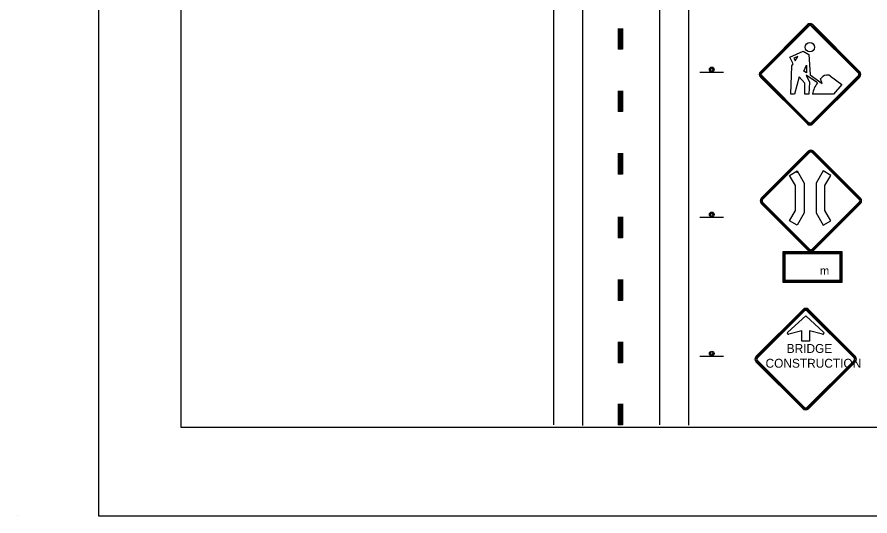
# Model space of a CAD drawing. Extents: x 1062 to 1288, y 239 to 518.
# Drawn here: x 1061.7 to 1165.3, y 238.9 to 299.6 of the extents above; entities that cross this region are included whole.
import ezdxf

# ---------------------------------------------------------------- set-up
doc = ezdxf.new("R2010")
doc.units = 0
for name, color, linetype in [('Level 10', 7, 'Continuous'), ('Level 17', 7, 'Continuous'), ('Level 44', 7, 'Continuous'), ('Level 60', 7, 'Continuous')]:
    doc.layers.add(name, color=color, linetype=linetype)

# ---------------------------------------------------------------- blocks, each defined once
blk = doc.blocks.new('WDA024')
at = {"layer": 'Level 17'}
for p, q in [((50.34, 50.34), (2.69, 2.69)), ((51.05, 49.64), (3.39, 1.98)), ((51.76, 48.94), (4.1, 1.27)), ((101.97, 1.27), (54.3, 48.94)), ((102.67, 1.98), (55.01, 49.64)), ((103.38, 2.69), (55.72, 50.34)), ((40.54, 24.59), (32.82, 20.13)), ((32.82, 20.13), (38.86, 9.73)), ((47.74, 12.11), (40.54, 24.59)), ((59.76, 12.11), (66.96, 24.59)), ((66.96, 24.59), (74.62, 20.13)), ((74.62, 20.13), (68.64, 9.73)), ((38.86, 9.73), (38.86, -15.46)), ((47.74, -17.84), (47.74, 12.11)), ((59.76, -17.84), (59.76, 12.11)), ((68.64, 9.73), (68.64, -15.46)), ((0, 0), (0, 0)), ((2.69, -2.69), (50.34, -50.35)), ((3.39, -1.98), (51.05, -49.64)), ((4.1, -1.27), (51.76, -48.93)), ((54.3, -48.93), (101.97, -1.27)), ((55.01, -49.64), (102.67, -1.98)), ((55.72, -50.35), (103.38, -2.69)), ((38.86, -15.46), (32.82, -25.86)), ((68.64, -15.46), (74.62, -25.86)), ((32.82, -25.86), (40.54, -30.27)), ((40.54, -30.27), (47.74, -17.84)), ((66.96, -30.27), (59.76, -17.84)), ((74.62, -25.86), (66.96, -30.27)), ((66.96, -30.27), (67.36, -28.58))]:
    blk.add_line(p, q, dxfattribs=at)
for centre, radius, start, end in [((53.03, 47.66), 3.8, 45, 135), ((53.03, 47.66), 2.8, 45, 135), ((53.03, 47.66), 1.8, 45, 135), ((5.37, 0), 3.8, 135, 225), ((5.37, 0), 2.8, 135, 225), ((5.37, 0), 1.8, 135, 225), ((100.69, 0), 1.8, 315, 45), ((100.69, 0), 2.8, 315, 45), ((100.69, 0), 3.8, 315, 45), ((53.03, -47.66), 3.8, 225, 315), ((53.03, -47.66), 2.8, 225, 315), ((53.03, -47.66), 1.8, 225, 315)]:
    blk.add_arc(centre, radius, start, end, dxfattribs=at)
blk = doc.blocks.new('WDB04T')
at = {"layer": 'Level 17'}
for points in [[(60.004, 0.004), (0.004, 0.004), (0.004, -30.671), (60.004, -30.671)], [(59.004, -0.996), (1.004, -0.996), (1.004, -29.671), (59.004, -29.671)], [(58.004, -1.996), (2.004, -1.996), (2.004, -28.671), (58.004, -28.671)]]:
    blk.add_lwpolyline(points, close=True, dxfattribs=at)
blk.add_text('m', height=8.373, dxfattribs=at).set_placement((37.562, -23.321))

msp = doc.modelspace()

# ---------------------------------------------------------------- linework, layer by layer
at = {"layer": 'Level 10'}
for p, q in [((1143.33, 249.99), (1143.33, 410.9)), ((1126.93, 250.01), (1126.93, 401.62)), ((1139.81, 250.01), (1139.81, 380.51)), ((1130.44, 249.95), (1130.44, 373.79))]:
    msp.add_line(p, q, dxfattribs=at)
at = {"layer": 'Level 17'}
for p, q in [((1157.75, 298.68), (1152.03, 292.96)), ((1164.11, 292.96), (1158.39, 298.68)), ((1157.83, 298.59), (1152.11, 292.88)), ((1157.92, 298.51), (1152.2, 292.79)), ((1163.94, 292.79), (1158.22, 298.51)), ((1164.03, 292.88), (1158.31, 298.59)), ((1151.71, 292.64), (1151.71, 292.64)), ((1152.11, 292.4), (1157.83, 286.68)), ((1152.2, 292.48), (1157.92, 286.76)), ((1158.22, 286.76), (1163.94, 292.48)), ((1158.31, 286.68), (1164.03, 292.4)), ((1160.56, 292.41), (1161.93, 291.41)), ((1160.56, 292.41), (1161.93, 291.41)), ((1152.03, 292.31), (1157.75, 286.6)), ((1158.39, 286.6), (1164.11, 292.31)), ((1159.32, 292.09), (1159.62, 292.36)), ((1159.32, 292.09), (1159.62, 292.36)), ((1151.49, 258.32), (1157.21, 264.04)), ((1151.58, 258.24), (1157.3, 263.96)), ((1151.66, 258.15), (1157.38, 263.87)), ((1157.69, 263.87), (1163.41, 258.15)), ((1157.77, 263.96), (1163.49, 258.24)), ((1157.86, 264.04), (1163.58, 258.32)), ((1155.47, 261.04), (1155.47, 261.04)), ((1155.47, 261.04), (1155.47, 261.04)), ((1155.47, 261.04), (1155.47, 261.04)), ((1151.17, 258), (1151.17, 258)), ((1157.21, 251.96), (1151.49, 257.68)), ((1157.3, 252.04), (1151.58, 257.76)), ((1157.38, 252.13), (1151.66, 257.85)), ((1163.41, 257.85), (1157.69, 252.13)), ((1163.49, 257.76), (1157.77, 252.04)), ((1163.58, 257.68), (1157.86, 251.96))]:
    msp.add_line(p, q, dxfattribs=at)
for points in [[(1158.96, 291.59), (1157.58, 292.54), (1157.98, 291.7), (1157.93, 290.24), (1157.45, 290.24), (1157.42, 291.56), (1156.75, 292.33), (1156.17, 290.24), (1155.75, 290.24), (1155.87, 293.69), (1156.03, 293.93), (1155.6, 294.74), (1157.22, 295.46), (1157.91, 295.06), (1158.07, 292.59), (1159.55, 291.52), (1159.32, 292.09)], [(1161.93, 291.41), (1160.92, 290.24), (1158.35, 290.24)], [(1155.35, 261.27), (1157.54, 263.26), (1159.72, 261.27)], [(1155.35, 261.27), (1157.54, 263.26), (1159.72, 261.27)], [(1155.35, 261.27), (1157.54, 263.26), (1159.72, 261.27)], [(1159.59, 261.04), (1157.99, 261.45), (1157.99, 260.2), (1157.08, 260.2), (1157.08, 261.45), (1155.47, 261.04)], [(1159.59, 261.04), (1157.99, 261.45), (1157.99, 260.2), (1157.08, 260.2), (1157.08, 261.45), (1155.47, 261.04)], [(1159.59, 261.04), (1157.99, 261.45), (1157.99, 260.2), (1157.08, 260.2), (1157.08, 261.45), (1155.47, 261.04)]]:
    msp.add_lwpolyline(points, dxfattribs=at)
for points in [[(1156.08, 294.59), (1156.25, 294.29), (1156.57, 294.79)], [(1157.32, 293.04), (1157.62, 293.75), (1157.65, 292.84)]]:
    msp.add_lwpolyline(points, close=True, dxfattribs=at)
msp.add_circle((1158.05, 295.93), 0.569, dxfattribs=at)
for centre, radius, start, end in [((1158.07, 298.36), 0.456, 45, 135), ((1158.07, 298.36), 0.336, 45, 135), ((1158.07, 298.36), 0.216, 45, 135), ((1152.35, 292.64), 0.456, 135, 225), ((1152.35, 292.64), 0.336, 135, 225), ((1152.35, 292.64), 0.216, 135, 225), ((1160.12, 291.8), 0.749, 53.9362, 131.97), ((1160.12, 291.8), 0.749, 53.9362, 131.97), ((1163.79, 292.64), 0.216, 315, 45), ((1163.79, 292.64), 0.336, 315, 45), ((1163.79, 292.64), 0.456, 315, 45), ((1161.82, 289.48), 3.55, 143.5617, 167.6366), ((1158.07, 286.92), 0.456, 225, 315), ((1158.07, 286.92), 0.336, 225, 315), ((1158.07, 286.92), 0.216, 225, 315), ((1157.54, 263.72), 0.456, 45, 135), ((1157.54, 263.72), 0.336, 45, 135), ((1157.54, 263.72), 0.216, 45, 135), ((1155.44, 261.17), 0.137, 132.3048, 284.4075), ((1155.44, 261.17), 0.137, 132.3048, 284.4075), ((1155.44, 261.17), 0.137, 132.3048, 284.4075), ((1159.63, 261.17), 0.137, 255.5925, 47.6952), ((1159.63, 261.17), 0.137, 255.5925, 47.6952), ((1159.63, 261.17), 0.137, 255.5925, 47.6952), ((1151.82, 258), 0.456, 135, 225), ((1151.82, 258), 0.336, 135, 225), ((1163.25, 258), 0.336, 315, 45), ((1163.25, 258), 0.456, 315, 45), ((1151.82, 258), 0.216, 135, 225), ((1163.25, 258), 0.216, 315, 45), ((1157.54, 252.28), 0.456, 225, 315), ((1157.54, 252.28), 0.336, 225, 315), ((1157.54, 252.28), 0.216, 225, 315)]:
    msp.add_arc(centre, radius, start, end, dxfattribs=at)
at = {"layer": 'Level 44'}
for p, q in [((1135.25, 295.7), (1134.73, 295.7)), ((1144.66, 292.92), (1147.56, 292.92)), ((1135.25, 288.1), (1134.73, 288.1)), ((1135.25, 280.5), (1134.73, 280.5)), ((1144.66, 275.27), (1147.56, 275.27)), ((1135.25, 272.75), (1134.73, 272.75)), ((1135.25, 265.15), (1134.73, 265.15)), ((1144.66, 258.36), (1147.56, 258.36)), ((1135.25, 257.55), (1134.73, 257.55)), ((1135.25, 250.03), (1134.73, 250.03))]:
    msp.add_line(p, q, dxfattribs=at)
for points in [[(1134.73, 298.23), (1134.73, 295.7)], [(1134.82, 298.23), (1134.82, 295.7)], [(1134.9, 298.23), (1134.9, 295.7)], [(1134.99, 298.23), (1134.99, 295.7)], [(1135.08, 298.23), (1135.08, 295.7)], [(1135.17, 298.23), (1135.17, 295.7)], [(1135.25, 298.23), (1135.25, 295.7)], [(1134.73, 290.63), (1134.73, 288.1)], [(1134.82, 290.63), (1134.82, 288.1)], [(1134.9, 290.63), (1134.9, 288.1)], [(1134.99, 290.63), (1134.99, 288.1)], [(1135.08, 290.63), (1135.08, 288.1)], [(1135.17, 290.63), (1135.17, 288.1)], [(1135.25, 290.63), (1135.25, 288.1)], [(1134.73, 283.04), (1134.73, 280.5)], [(1134.82, 283.04), (1134.82, 280.5)], [(1134.9, 283.04), (1134.9, 280.5)], [(1134.99, 283.04), (1134.99, 280.5)], [(1135.08, 283.04), (1135.08, 280.5)], [(1135.17, 283.04), (1135.17, 280.5)], [(1135.25, 283.04), (1135.25, 280.5)], [(1134.73, 275.29), (1134.73, 272.75)], [(1134.82, 275.29), (1134.82, 272.75)], [(1134.9, 275.29), (1134.9, 272.75)], [(1134.99, 275.29), (1134.99, 272.75)], [(1135.08, 275.29), (1135.08, 272.75)], [(1135.17, 275.29), (1135.17, 272.75)], [(1135.25, 275.29), (1135.25, 272.75)], [(1134.73, 267.69), (1134.73, 265.15)], [(1134.82, 267.69), (1134.82, 265.15)], [(1134.9, 267.69), (1134.9, 265.15)], [(1134.99, 267.69), (1134.99, 265.15)], [(1135.08, 267.69), (1135.08, 265.15)], [(1135.17, 267.69), (1135.17, 265.15)], [(1135.25, 267.69), (1135.25, 265.15)], [(1134.73, 260.09), (1134.73, 257.55)], [(1134.82, 260.09), (1134.82, 257.55)], [(1134.9, 260.09), (1134.9, 257.55)], [(1134.99, 260.09), (1134.99, 257.55)], [(1135.08, 260.09), (1135.08, 257.55)], [(1135.17, 260.09), (1135.17, 257.55)], [(1135.25, 260.09), (1135.25, 257.55)], [(1134.73, 252.56), (1134.73, 250.03)], [(1134.82, 252.56), (1134.82, 250.03)], [(1134.9, 252.56), (1134.9, 250.03)], [(1134.99, 252.56), (1134.99, 250.03)], [(1135.08, 252.56), (1135.08, 250.03)], [(1135.17, 252.56), (1135.17, 250.03)], [(1135.25, 252.56), (1135.25, 250.03)]]:
    msp.add_lwpolyline(points, dxfattribs=at)
for centre, radius in [((1146.12, 293.24), 0.29), ((1146.12, 293.24), 0.145), ((1146.12, 275.6), 0.29), ((1146.12, 275.6), 0.145), ((1146.12, 258.68), 0.29), ((1146.12, 258.68), 0.145)]:
    msp.add_circle(centre, radius, dxfattribs=at)
at = {"layer": 'Level 60'}
for p, q in [((1081.56, 249.74), (1081.56, 249.74)), ((1061.67, 238.93), (1061.67, 238.93))]:
    msp.add_line(p, q, dxfattribs=at)
for points in [[(1287.56, 517.93), (1071.56, 517.93), (1071.56, 238.93), (1287.56, 238.93)], [(1268.44, 507.12), (1081.56, 507.12), (1081.56, 249.74), (1268.44, 249.74)]]:
    msp.add_lwpolyline(points, close=True, dxfattribs=at)

# ---------------------------------------------------------------- block references
at = {"layer": 'Level 17', "xscale": 0.12, "yscale": 0.12, "rotation": 179.99999999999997}
msp.add_blockref('WDA024', (1164.53, 277.25), dxfattribs=at)
at = {"layer": 'Level 17', "xscale": 0.12, "yscale": 0.12}
msp.add_blockref('WDB04T', (1154.77, 271.06), dxfattribs=at)

# ---------------------------------------------------------------- texts
at = {"layer": 'Level 17'}
for s, p in [('BRIDGE', (1155.23, 258.76)), ('CONSTRUCTION', (1152.66, 256.96))]:
    msp.add_text(s, height=1.08, dxfattribs=at).set_placement(p)

doc.saveas('drawing.dxf')
